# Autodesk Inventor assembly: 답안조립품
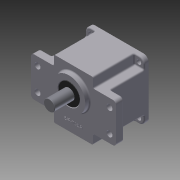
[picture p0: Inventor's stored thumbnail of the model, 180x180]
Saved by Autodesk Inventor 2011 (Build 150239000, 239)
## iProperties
Created: 2014-12
Part Number: 답안조립품
Document SubType Name: Assembly
Designer: Administrator
Author: Administrator
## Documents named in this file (12)
- C:\Documents and Settings\Administrator\바탕 화면\Inventor2급-류성호\답안조립품.iam
- C:\Documents and Settings\Administrator\바탕 화면\Inventor2급-류성호\본체.ipt
- C:\Documents and Settings\Administrator\바탕 화면\Inventor2급-류성호\오일실 17x32x8.ipt
- C:\Documents and Settings\Administrator\바탕 화면\Inventor2급-류성호\베어링 6003.ipt
- 베어링 6003.ipt
- C:\Documents and Settings\Administrator\바탕 화면\Inventor2급-류성호\베어링 608.ipt
- 베어링 608.ipt
- C:\Documents and Settings\Administrator\바탕 화면\Inventor2급-류성호\서브축.ipt
- C:\Documents and Settings\Administrator\바탕 화면\Inventor2급-류성호\메인축.ipt
- C:\Documents and Settings\Administrator\바탕 화면\Inventor2급-류성호\커버.ipt
- C:\Documents and Settings\Administrator\바탕 화면\Inventor2급-류성호\오일실 8x22x7.ipt
- C:\Documents and Settings\Administrator\바탕 화면\Inventor2급-류성호\M4x0.5x16.ipt
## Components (4 placed, 1 different names)
1. M4x0.5x12:1
2. M4x0.5x12:2
3. M4x0.5x12:3
4. M4x0.5x12:4
